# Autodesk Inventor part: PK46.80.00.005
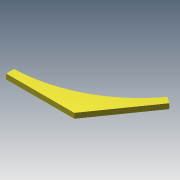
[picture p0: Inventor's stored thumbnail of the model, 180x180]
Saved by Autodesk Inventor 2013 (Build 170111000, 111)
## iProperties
Shininess: 64.0
Length Units: 11269
Angle Units: 11279
Time Units: 11290
Mass Units: 11283
Length Display Precision: 3
Angle Display Precision: 2
Compacted: True
Part Number: PK46.80.00.005
Document SubType Name: Modeling
Created: 2005-01
Material: Steel, Mild
Designer: SAlex
Manufacturer: Standard
Standards Organization: Custom
Density: 7.86 g/cm^3
Mass: 2156.78 g
Surface Area: 479.373 cm^2
Volume: 274.4 cm^3
Density: 0.0
Volumn: 0.0
Area: 0.0
PropertySet Name: Model Information
Control State: 0
Master: False
Checked Out: False
Checked Out Date: 2008-10-15
Last Check In Date: 2008-10-15
Author: SAlex
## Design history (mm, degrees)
sketch "Sketch1"
  geometry: L1 (0, 0)-(0, -25); L2 (0, -25)-(215.342, -25); L3 (215.342, -25)-(338.857, 151.398); L4 (338.857, 151.398)-(318.378, 165.737); L5 (-10, -36.05)-(-10, 407.877); L6 (-10, 407.877)-(215.342, -25); L7 (-10, 407.877)-(372.226, 140.24); A1 r 408 centre (-10, 407.877) between (0, 0) and (318.378, 165.737)
  constraints: 14 end point, 3 perpendicular, 2 point on circle, 1 centre point, 1 parallel, 1 vertical, 1 other
  dimensions: "d0" = 408 radius of A1; "d1" = 25 distance of L1.start L1.end; "d9" = 10 distance between parallel lines of L1 L5; "d10" = 10 distance between parallel lines of L4 L7; "d11" = 55 deg angle of L7 L5; "d12" = 27.5 deg angle of L7 L6 (= 0.5 x d11)
extrude "Extrusion1" new body sketch "Sketch1" distance "d7" = 16; taper "d8" = 0 deg
body "Solid1"
